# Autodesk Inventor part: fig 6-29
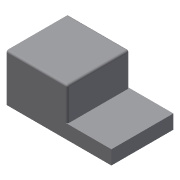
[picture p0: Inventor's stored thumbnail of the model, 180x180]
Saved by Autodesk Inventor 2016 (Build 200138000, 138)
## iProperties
Created: 2004-05
Part Number: fig 6-29
Document SubType Name: Modeling
Designer: CADCIM Technologies
Manufacturer: Standard
Standards Organization: Custom
Density: 1 g/cm^3
Material: Generic
Appearance: Default
Author: CADCIM Technologies
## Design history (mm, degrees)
node "Sketch1"
sketch "Sketch2"
  geometry: L1 (0.098, 47.711)-(0.098, 0.049); L2 (0.098, 0.049)-(-105.483, 0.049); L3 (-105.483, 0.049)-(-105.483, 14.192); L4 (-105.483, 14.192)-(-61.139, 14.192); L5 (-61.139, 14.192)-(-61.139, 47.711); L6 (-61.139, 47.711)-(0.098, 47.711)
  constraints: 12 end point, 3 parallel, 2 perpendicular, 1 vertical
extrude "Extrusion1" new body sketch "Sketch2" stored distance "d0" = 62.5; taper "d1" = 0 deg
fillet "Fillet6" dims "d44" = 2, "d45" = 2, "d46" = 2, "d47" = 2, "d48" = 2, "d49" = 2
body "Solid1"
